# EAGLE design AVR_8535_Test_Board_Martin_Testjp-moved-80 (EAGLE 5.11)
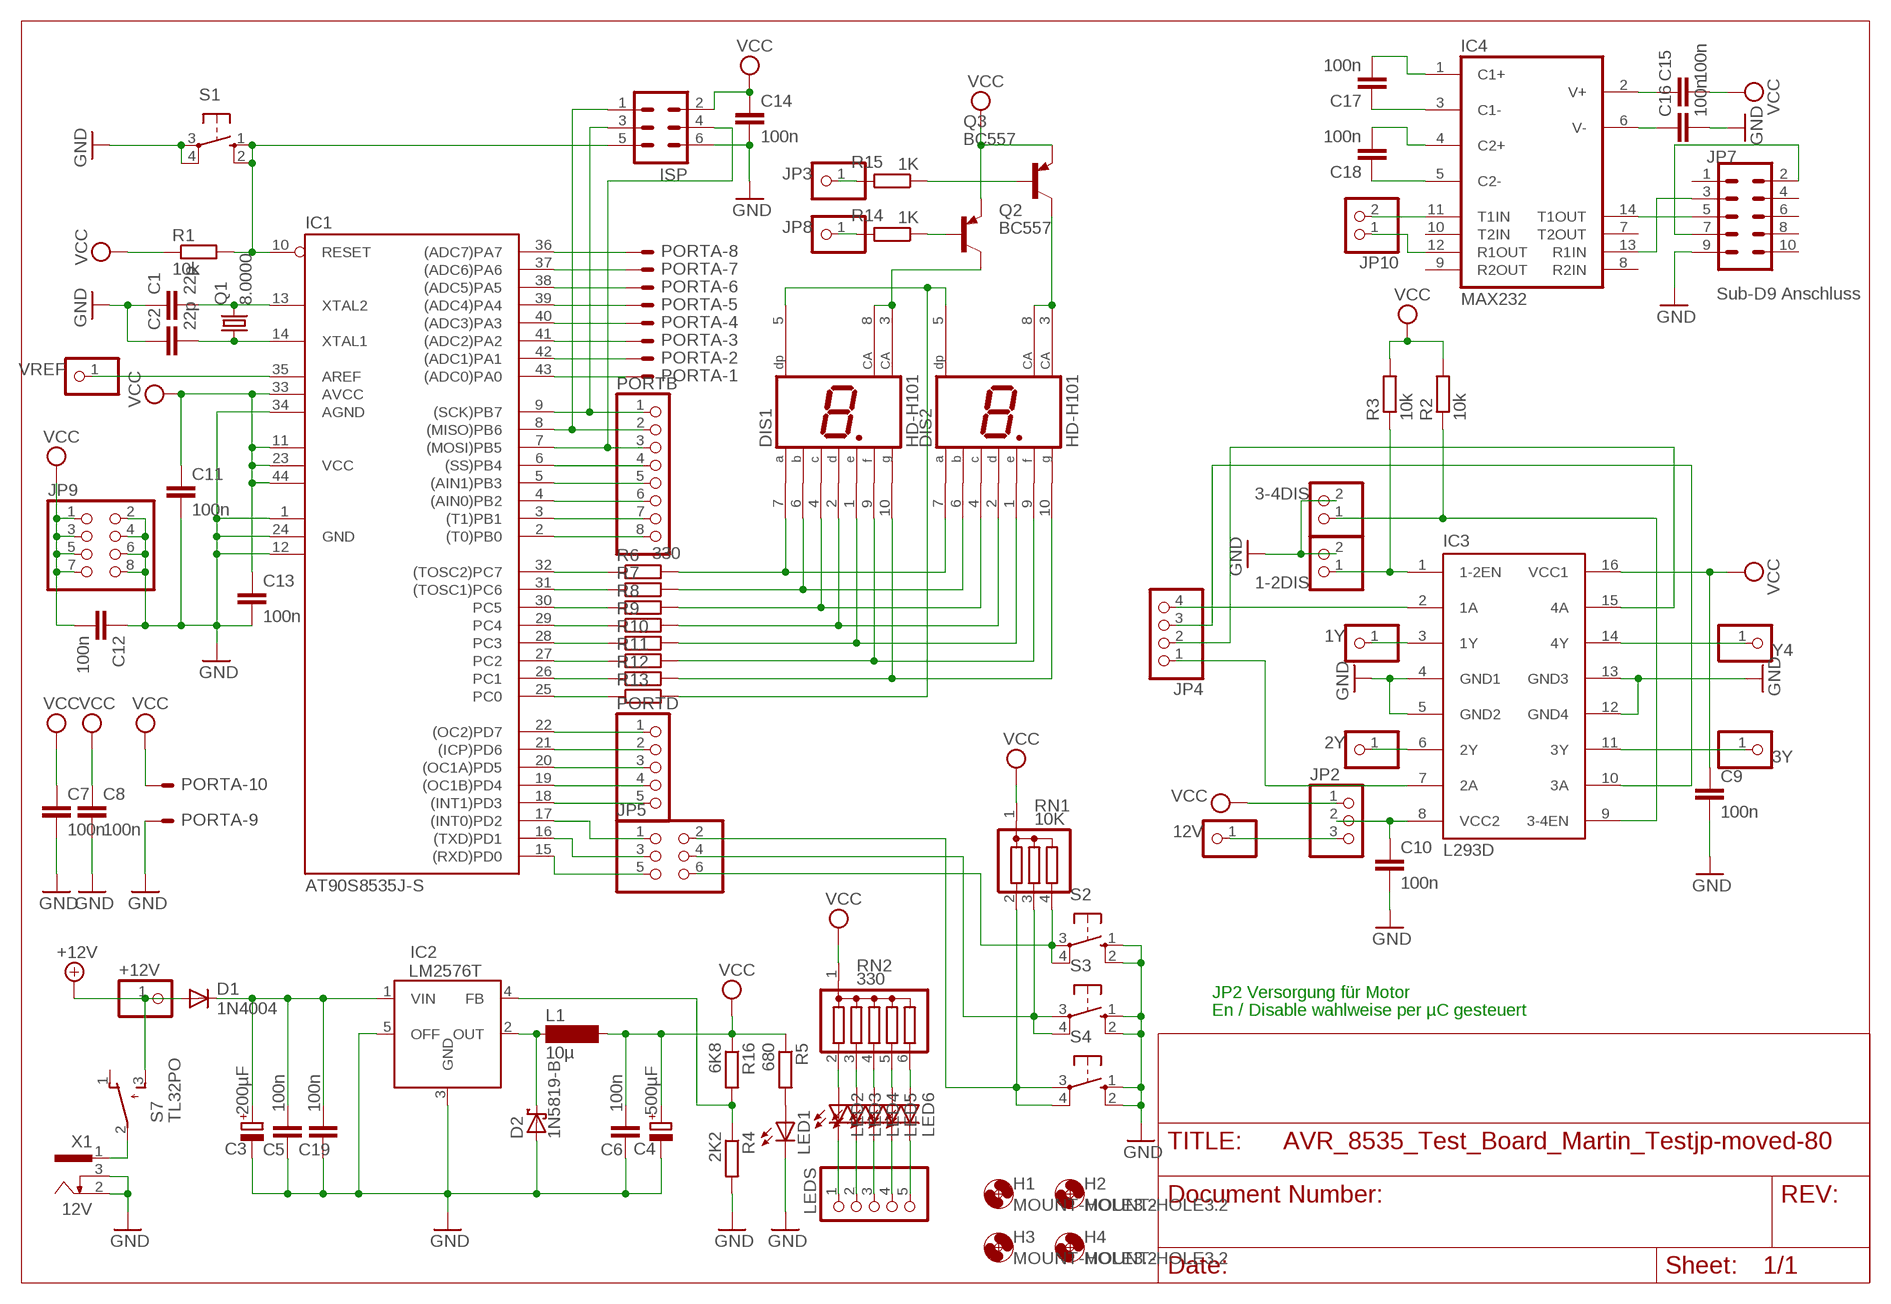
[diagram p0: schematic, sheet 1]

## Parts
1-2DIS  PINHD-1X2  [1X02]
1Y  PINHD-1X1  [1X01]
2Y  PINHD-1X1  [1X01]
3-4DIS  PINHD-1X2  [1X02]
3Y  PINHD-1X1  [1X01]
12V  PINHD-1X1  [1X01]
+12V  PINHD-1X1  [1X01]
C1  22p  C-EU025-024X044  [C025-024X044]
C2  22p  C-EU025-024X044  [C025-024X044]
C3  200µF  CPOL-EUE3.5-10  [E3,5-10]
C4  500µF  CPOL-EUE3.5-10  [E3,5-10]
C5  100n  C-EU050-024X044  [C050-024X044]
C6  100n  C-EU050-024X044  [C050-024X044]
C7  100n  C-EU025-024X044  [C025-024X044]
C8  100n  C-EU025-024X044  [C025-024X044]
C9  100n  C-EU050-024X044  [C050-024X044]
C10  100n  C-EU050-024X044  [C050-024X044]
C11  100n  C-EU050-024X044  [C050-024X044]
C12  100n  C-EU025-024X044  [C025-024X044]
C13  100n  C-EU025-024X044  [C025-024X044]
C14  100n  C-EU050-024X044  [C050-024X044]
C15  100n  C-EU025-024X044  [C025-024X044]
C16  100n  C-EU025-024X044  [C025-024X044]
C17  100n  C-EU050-024X044  [C050-024X044]
C18  100n  C-EU025-024X044  [C025-024X044]
C19  100n  C-EU050-024X044  [C050-024X044]
D1  1N4004  [DO41-10]
D2  1N5819-B  [DO41-7.6]
DIS1  HD-H101  [HDSP-M]
DIS2  HD-H101  [HDSP-M]
H1  MOUNT-HOLE3.2  [3,2]
H2  MOUNT-HOLE3.2  [3,2]
H3  MOUNT-HOLE3.2  [3,2]
H4  MOUNT-HOLE3.2  [3,2]
IC1  AT90S8535J-S  [S44]
IC2  LM2576T  [TO220-5]
IC3  L293D  [DIL16]
IC4  MAX232  [DIL16]
ISP  ML6  [ML6]
JP2  PINHD-1X3  [1X03]
JP3  PINHD-1X1  [1X01]
JP4  PINHD-1X4  [1X04]
JP5  PINHD-2X3  [2X03]
JP7  Sub-D9 Anschluss  ML10  [ML10]
JP8  PINHD-1X1  [1X01]
JP9  PINHD-2X4  [2X04]
JP10  PINHD-1X2  [1X02]
L1  10µ  SD75  [SD75]
LED1  LED3MM  [LED3MM]
LED2  LED3MM  [LED3MM]
LED3  LED3MM  [LED3MM]
LED4  LED3MM  [LED3MM]
LED5  LED3MM  [LED3MM]
LED6  LED3MM  [LED3MM]
LEDS  PINHD-1X5  [1X05]
PORTA  ML10E  [ML10]
PORTB  PINHD-1X8  [1X08]
PORTD  PINHD-1X5  [1X05]
Q1  8.0000  CRYSTALHC49U-V  [HC49U-V]
Q2  BC557  [TO92-EBC]
Q3  BC557  [TO92-EBC]
R1  10k  R-EU_0204/5  [0204/5]
R2  10k  R-EU_0204/5  [0204/5]
R3  10k  R-EU_0204/7  [0204/7]
R4  2K2  R-EU_0204/7  [0204/7]
R5  680  R-EU_0207/10  [0207/10]
R6  330  R-EU_0207/10  [0207/10]
R7  R-EU_0207/10  [0207/10]
R8  R-EU_0207/10  [0207/10]
R9  R-EU_0207/10  [0207/10]
R10  R-EU_0207/10  [0207/10]
R11  R-EU_0207/10  [0207/10]
R12  R-EU_0207/10  [0207/10]
R13  R-EU_0207/10  [0207/10]
R14  1K  R-EU_0204/2V  [0204V]
R15  1K  R-EU_0204/2V  [0204V]
R16  6K8  R-EU_0204/7  [0204/7]
RN1  10K  G03R  [SIL4]
RN2  330  G05R  [SIL6]
S1  10-XX  [B3F-10XX]
S2  10-XX  [B3F-10XX]
S3  10-XX  [B3F-10XX]
S4  10-XX  [B3F-10XX]
S7  TL32PO  [TL3XPO]
VREF  PINHD-1X1  [1X01]
X1  12V  SCD-014A  [SCD-014-A]
Y4  PINHD-1X1  [1X01]

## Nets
+12V: +12V.1 D1.A S7.3(S)
GND: 1-2DIS.2 3-4DIS.2 C1.1 C2.1 C3.- C4.- C5.2 C6.2 C7.2 C8.2 C9.2 C10.2 C11.2 C12.1 C13.2 C14.2 C16.2 C19.2 D2.A IC1.1(GND1) IC1.12(GND2) IC1.24(GND) IC1.34(AGND) IC2.3(GND) IC2.5(OFF) IC3.4(GND1) IC3.5(GND2) IC3.12(GND4) IC3.13(GND3) ISP.6 JP7.9 JP9.2 JP9.4 JP9.6 JP9.8 LED1.K(C) PORTA.9 R4.2 S1.3(P) S1.4(P1) S2.1(S) S2.2(S1) S3.1(S) S3.2(S1) S4.1(S) S4.2(S1) X1.2 X1.3
N$1: C10.1 IC3.8(VCC2) JP2.2
N$2: IC3.14(4Y) Y4.1
N$3: C3.+ C5.1 C19.1 D1.C IC2.1(VIN)
N$4: C1.2 IC1.13(XTAL2) Q1.2
N$5: C2.2 IC1.14(XTAL1) Q1.1
N$6: IC1.36((ADC7)PA7) PORTA.8
N$7: IC1.37((ADC6)PA6) PORTA.7
N$8: IC1.38((ADC5)PA5) PORTA.6
N$9: IC1.39((ADC4)PA4) PORTA.5
N$10: JP8.1 R14.2
N$11: IC1.2((T0)PB0) PORTB.8
N$12: IC3.2(1A) JP4.4
N$13: IC3.7(2A) JP4.1
N$14: IC3.10(3A) JP4.3
N$15: IC3.15(4A) JP4.2
N$16: IC1.8((MISO)PB6) ISP.1 PORTB.2
N$17: IC1.9((SCK)PB7) ISP.3 PORTB.1
N$18: IC1.40((ADC3)PA3) PORTA.4
N$19: IC1.41((ADC2)PA2) PORTA.3
N$20: IC1.42((ADC1)PA1) PORTA.2
N$21: IC1.43((ADC0)PA0) PORTA.1
N$22: LED1.A R5.2
N$23: IC1.32((TOSC2)PC7) R6.1
N$24: IC1.31((TOSC1)PC6) R7.1
N$25: IC1.30(PC5) R8.1
N$26: IC1.29(PC4) R9.1
N$27: IC1.28(PC3) R10.1
N$28: IC1.27(PC2) R11.1
N$29: IC1.26(PC1) R12.1
N$30: LED6.A RN2.6
N$31: JP5.6 RN1.4 S2.3(P) S2.4(P1)
N$32: C15.1 IC4.2(V+)
N$33: 3Y.1 IC3.11(3Y)
N$34: LED6.K(C) LEDS.5
N$35: 1Y.1 IC3.3(1Y)
N$36: 2Y.1 IC3.6(2Y)
N$37: JP5.4 RN1.3 S3.3(P) S3.4(P1)
N$38: JP5.2 RN1.2 S4.3(P) S4.4(P1)
N$39: IC1.25(PC0) R13.1
N$40: IC1.17((INT0)PD2) JP5.1
N$41: DIS1.7(A) DIS2.7(A) R6.2
N$42: DIS1.6(B) DIS2.6(B) R7.2
N$43: DIS1.4(C) DIS2.4(C) R8.2
N$44: DIS1.2(D) DIS2.2(D) R9.2
N$45: DIS1.1(E) DIS2.1(E) R10.2
N$46: DIS1.9(F) DIS2.9(F) R11.2
N$47: DIS1.10(G) DIS2.10(G) R12.2
N$48: DIS1.3(CA) DIS1.8(CA) Q2.C
N$49: DIS2.3(CA) DIS2.8(CA) Q3.C
N$50: DIS1.5(DP) DIS2.5(DP) R13.2
N$51: Q3.B R15.1
N$52: Q2.B R14.1
N$53: D2.C IC2.2(OUT) L1.1
N$54: 3-4DIS.1 IC3.9(3-4EN) R2.1
N$55: IC1.16((TXD)PD1) JP5.3
N$56: IC1.4((AIN0)PB2) PORTB.6
N$57: IC1.5((AIN1)PB3) PORTB.5
N$58: IC1.6((SS)PB4) PORTB.4
N$59: IC1.7((MOSI)PB5) ISP.4 PORTB.3
N$60: S7.2(P) X1.1
N$61: IC1.22((OC2)PD7) PORTD.1
N$62: IC1.21((ICP)PD6) PORTD.2
N$63: IC1.20((OC1A)PD5) PORTD.3
N$64: IC1.19((OC1B)PD4) PORTD.4
N$65: IC1.15((RXD)PD0) JP5.5
N$66: LED2.K(C) LEDS.1
N$67: LED3.K(C) LEDS.2
N$68: LED4.K(C) LEDS.3
N$69: 12V.1 JP2.3
N$70: JP3.1 R15.2
N$71: IC1.3((T1)PB1) PORTB.7
N$72: IC1.35(AREF) VREF.1
N$73: LED5.K(C) LEDS.4
N$74: IC1.18((INT1)PD3) PORTD.5
N$75: IC1.10(RESET) ISP.5 R1.2 S1.1(S) S1.2(S1)
N$76: C16.1 IC4.6(V-)
N$77: LED5.A RN2.5
N$78: LED4.A RN2.4
N$79: LED3.A RN2.3
N$80: LED2.A RN2.2
N$81: C17.1 IC4.3(C1-)
N$82: C17.2 IC4.1(C1+)
N$83: C18.1 IC4.5(C2-)
N$84: C18.2 IC4.4(C2+)
N$85: IC4.14(T1OUT) JP7.5
N$86: IC4.13(R1IN) JP7.3
N$87: JP7.2 JP7.7
N$88: IC4.11(T1IN) JP10.2
N$89: IC4.12(R1OUT) JP10.1
N$90: IC2.4(FB) R4.1 R16.2
N$92: 1-2DIS.1 IC3.1(1-2EN) R3.1
VCC: C4.+ C6.1 C7.1 C8.1 C9.1 C11.1 C12.2 C13.1 C14.1 C15.2 IC1.11(VCC1) IC1.23(VCC) IC1.33(AVCC) IC1.44(VCC2) IC3.16(VCC1) ISP.2 JP2.1 JP9.1 JP9.3 JP9.5 JP9.7 L1.2 PORTA.10 Q2.E Q3.E R1.1 R2.2 R3.2 R5.1 R16.1 RN1.1 RN2.1
Unconnected: IC4.7(T2OUT) IC4.8(R2IN) IC4.9(R2OUT) IC4.10(T2IN) JP7.1 JP7.4 JP7.6 JP7.8 JP7.10 S7.1(O)

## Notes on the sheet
- JP2 Versorgung für Motor
- En / Disable wahlweise per µC gesteuert

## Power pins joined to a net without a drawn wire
GND: IC4.15(GND)
VCC: IC4.16(VCC)

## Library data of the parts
1-2DIS 3-4DIS JP10 = pinhead:PINHD-1X2: PIN HEADER
1Y 2Y 3Y 12V +12V JP3 JP8 VREF Y4 = pinhead:PINHD-1X1: PIN HEADER
C1 C2 C7-C18 = rcl:C-EU: CAPACITOR, European symbol
C3 C4 = rcl:CPOL-EU: POLARIZED CAPACITOR, European symbol
C5 C6 C19 = resistor:C-EU: CAPACITOR, European symbol
D1 = diode:1N4004: DIODE
D2 = diode:1N581*: 1.0A SCHOTTKY BARRIER RECTIFIER
DIS1 DIS2 = display-hp:HD-H101: LED DISPLAY 1-character 7 segment, decimal point right; OC_FARNELL: unknown; OC_NEWARK: unknown
H1-H4 = holes:MOUNT-HOLE: MOUNTING HOLE with drill center marker
IC1 = atmel:AT90*8535: MICROCONTROLLER 8 Kbytes FLASH 512 bytes SRAM 512 bytes EEPROM UART 8-channel 10 bit ADC; OC_FARNELL: unknown; OC_NEWARK: unknown
IC2 = v-reg-JP:LM2576: National Semiconductor 3.0A "Simple Switcher"(c) 52kHz, Vout 1.23-37V (HV: 57V), Vin 40V (HV: 60V), 50µA standby current
IC3 = st-microelectronics:L293D: PUSH-PULL 4 CHANNEL DRIVER; MPN: L293D; OC_FARNELL: 9589619; OC_NEWARK: 56P8249
IC4 = maxim:MAX232: RS232 TRANSEIVER; MF: MAXIM; MPN: MAX232ACPE+; OC_FARNELL: 9723773; OC_NEWARK: 68K4544
ISP = con-harting-ml:ML6: HARTING; OC_FARNELL: unknown; OC_NEWARK: unknown
JP2 = pinhead:PINHD-1X3: PIN HEADER
JP4 = pinhead:PINHD-1X4: PIN HEADER
JP5 = pinhead:PINHD-2X3: PIN HEADER
JP7 = con-harting-ml:ML10: HARTING; OC_FARNELL: unknown; OC_NEWARK: unknown
JP9 = pinhead:PINHD-2X4: PIN HEADER
L1 = inductor-neosid:SD75: INDUCTOR; OC_FARNELL: unknown; OC_NEWARK: unknown
LED1-LED6 = led:LED: LED
LEDS PORTD = pinhead:PINHD-1X5: PIN HEADER
PORTA = con-harting-ml:ML10?E: HARTING; OC_FARNELL: unknown; OC_NEWARK: unknown
PORTB = pinhead:PINHD-1X8: PIN HEADER
Q1 = crystal:CRYSTAL: CRYSTAL; OC_FARNELL: 1666969; OC_NEWARK: unknown
Q2 Q3 = transistor-pnp:BC557*: PNP Transistror
R1-R16 = rcl:R-EU_: RESISTOR, European symbol
RN1 = resistor-sil:G03R: SIL RESISTOR; OC_FARNELL: unknown; OC_NEWARK: unknown
RN2 = resistor-sil:G05R: SIL RESISTOR; OC_FARNELL: unknown; OC_NEWARK: unknown
S1-S4 = switch-omron:10-XX: OMRON SWITCH; MPN: B3F-1000; OC_FARNELL: 176432; OC_NEWARK: 36M3542
S7 = switch:TL32PO: TINY SWITCH ON - MOM Source: http://www2.produktinfo.conrad.com/datenblaetter/700000-724999/705152-da-01-de-Subminiaturschalter_TL_36YO.pdf
X1 = con-shiua-chyuan:SCD-014A: Power Jack 2.5mm; OC_FARNELL: unknown; OC_NEWARK: unknown

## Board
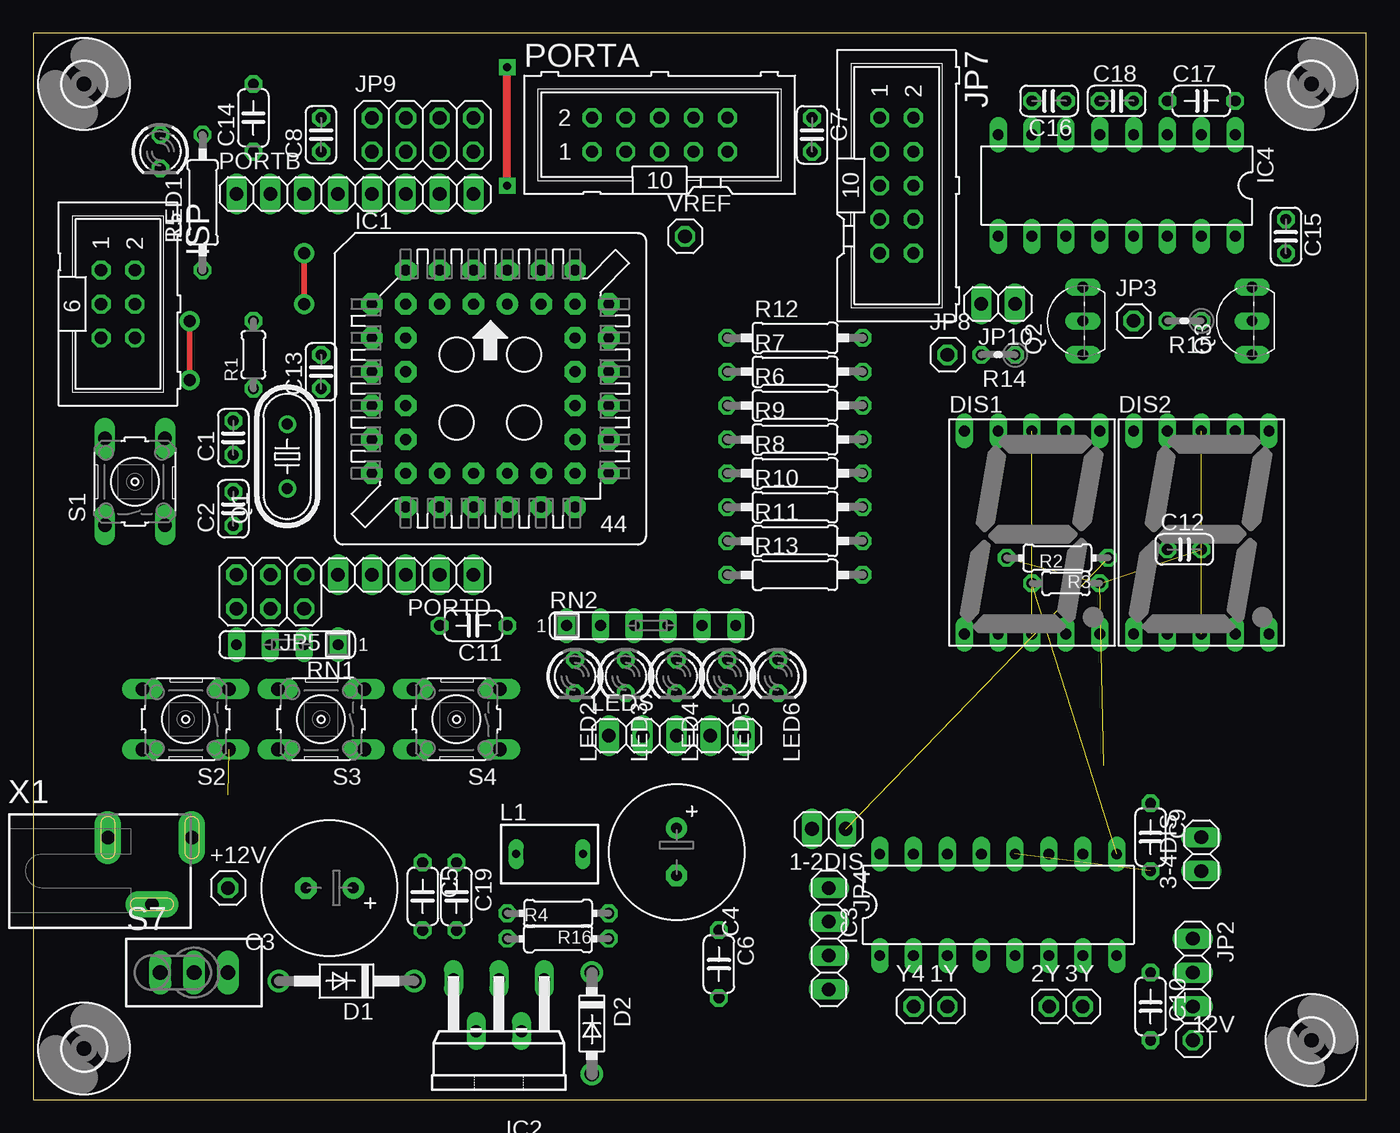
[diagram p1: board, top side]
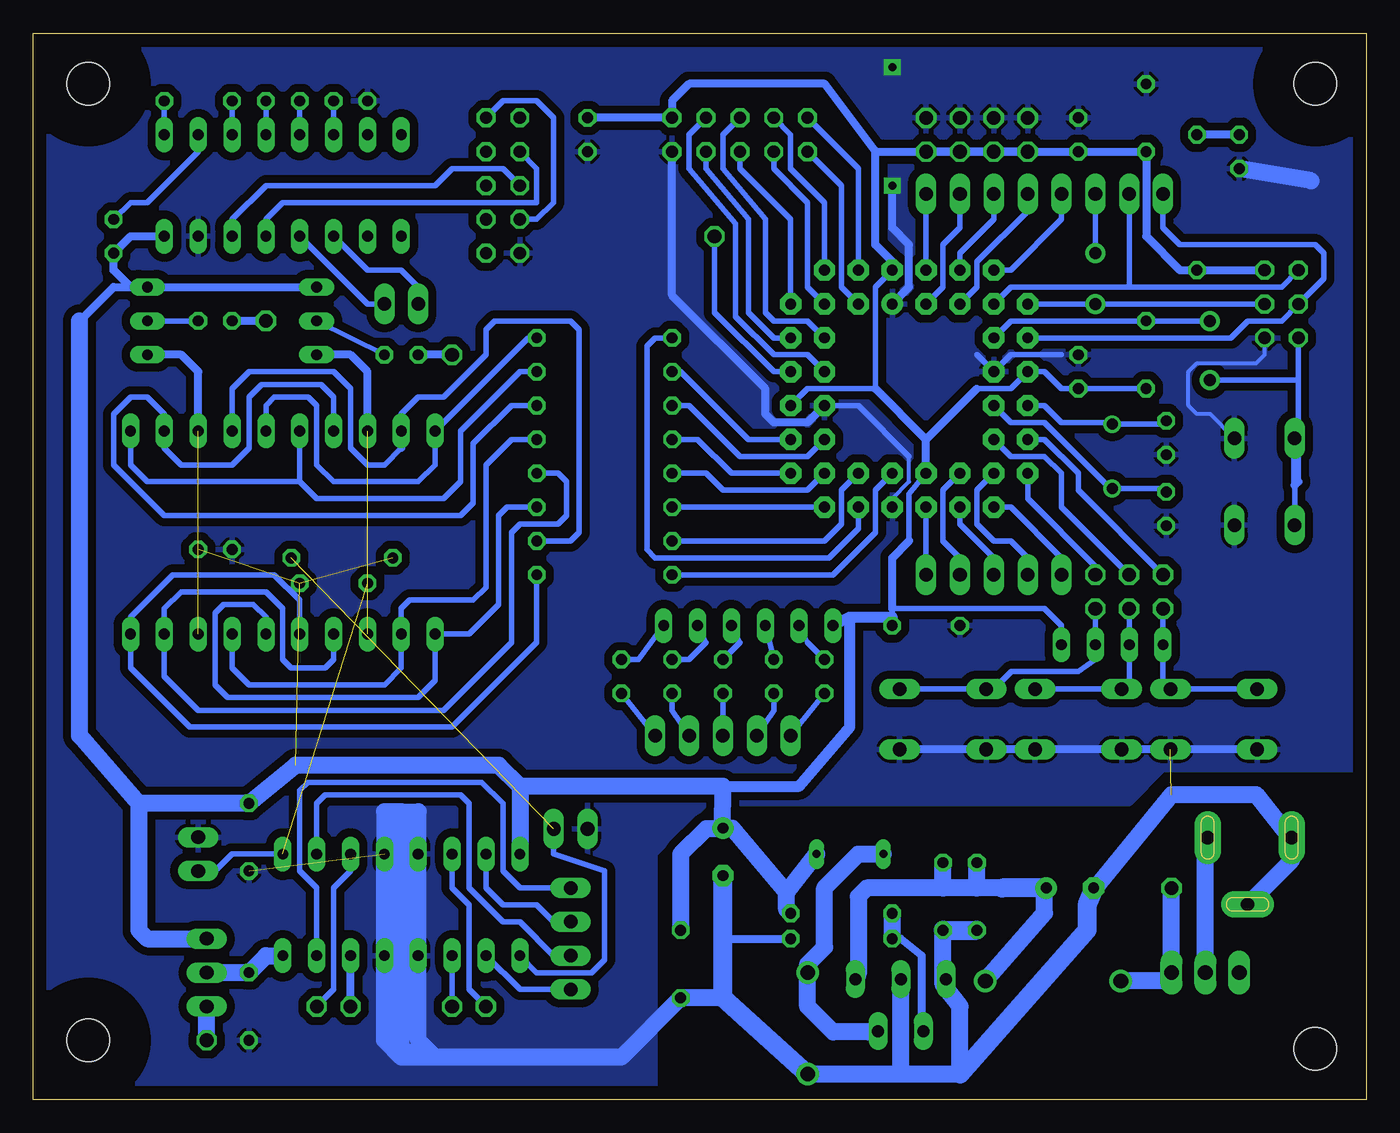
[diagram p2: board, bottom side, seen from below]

Size 100 x 80 mm. Coordinates in mm from the lower left corner, seen from the top.
Outline: 0,0 100,0 100,80 0,80 0,0
Copper layers (1*16): Top 0.035mm / dielectric 1.5mm / Bottom 0.035mm
Design rules "default *": minimum track width 10mil, minimum drill 24mil, track to track 8mil, track to pad 8mil, pad to pad 8mil, via to via 8mil, smd to smd 8mil, copper to edge 40mil, drill to drill 8mil, minimum pad ring 10mil, minimum via ring 12mil, stop-mask expansion 4mil, vias tented up to drill 0mil, thermal gap 10mil

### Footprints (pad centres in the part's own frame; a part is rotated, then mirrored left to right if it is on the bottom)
1X02 = drill 1.016 long: 1 -1.27,0; 2 1.27,0
1X01 = drill 1.016 octagon: 1 0,0
C025-024X044 = drill 0.813 octagon: 1 -1.27,0; 2 1.27,0
E3,5-10 = drill 0.813 pad 1.6 round: + -1.778,0 | drill 0.813 pad 1.6 octagon: - 1.778,0
C050-024X044 = drill 0.813 octagon: 1 -2.54,0; 2 2.54,0
DO41-10 = drill 1.118 round: A 5.08,0; C -5.08,0
DO41-7.6 = drill 1.1 pad 1.7 round: A 3.81,0; C -3.81,0
HDSP-M = drill 0.813 long: 1 -5.08,-7.62; 2 -2.54,-7.62; 3 0,-7.62; 4 2.54,-7.62; 5 5.08,-7.62; 6 5.08,7.62; 7 2.54,7.62; 8 0,7.62; 9 -2.54,7.62; 10 -5.08,7.62
3,2 = hole 3.2: 0,0
S44 = drill 0.813 pad 1.6 round: 1 1.27,6.35 | drill 0.813 pad 1.6 octagon: 2 -1.27,8.89; 3 -1.27,6.35; 4 -3.81,8.89; 5 -3.81,6.35; 6 -6.35,8.89; 7 -8.89,6.35; 8 -6.35,6.35; 9 -8.89,3.81; 10 -6.35,3.81; 11 -8.89,1.27; 12 -6.35,1.27; 13 -8.89,-1.27; 14 -6.35,-1.27; 15 -8.89,-3.81; 16 -6.35,-3.81; 17 -8.89,-6.35; 18 -6.35,-8.89; 19 -6.35,-6.35; 20 -3.81,-8.89; 21 -3.81,-6.35; 22 -1.27,-8.89; 23 -1.27,-6.35; 24 1.27,-8.89; 25 1.27,-6.35; 26 3.81,-8.89; 27 3.81,-6.35; 28 6.35,-8.89; 29 8.89,-6.35; 30 6.35,-6.35; 31 8.89,-3.81; 32 6.35,-3.81; 33 8.89,-1.27; 34 6.35,-1.27; 35 8.89,1.27; 36 6.35,1.27; 37 8.89,3.81; 38 6.35,3.81; 39 8.89,6.35; 40 6.35,8.89; 41 6.35,6.35; 42 3.81,8.89; 43 3.81,6.35; 44 1.27,8.89
TO220-5 = drill 0.9 long: 1 -3.4,-5.86; 2 -1.7,-1.96; 3 0,-5.86; 4 1.7,-1.96; 5 3.4,-5.86
DIL16 = drill 0.813 long: 1 -8.89,-3.81; 2 -6.35,-3.81; 3 -3.81,-3.81; 4 -1.27,-3.81; 5 1.27,-3.81; 6 3.81,-3.81; 7 6.35,-3.81; 8 8.89,-3.81; 9 8.89,3.81; 10 6.35,3.81; 11 3.81,3.81; 12 1.27,3.81; 13 -1.27,3.81; 14 -3.81,3.81; 15 -6.35,3.81; 16 -8.89,3.81
ML6 = drill 0.914 octagon: 1 -2.54,-1.27; 2 -2.54,1.27; 3 0,-1.27; 4 0,1.27; 5 2.54,-1.27; 6 2.54,1.27
1X03 = drill 1.016 long: 1 -2.54,0; 2 0,0; 3 2.54,0
1X04 = drill 1.016 long: 1 -3.81,0; 2 -1.27,0; 3 1.27,0; 4 3.81,0
2X03 = drill 1.016 octagon: 1 -2.54,-1.27; 2 -2.54,1.27; 3 0,-1.27; 4 0,1.27; 5 2.54,-1.27; 6 2.54,1.27
ML10 = drill 0.914 octagon: 1 -5.08,-1.27; 2 -5.08,1.27; 3 -2.54,-1.27; 4 -2.54,1.27; 5 0,-1.27; 6 0,1.27; 7 2.54,-1.27; 8 2.54,1.27; 9 5.08,-1.27; 10 5.08,1.27
2X04 = drill 1.016 octagon: 1 -3.81,-1.27; 2 -3.81,1.27; 3 -1.27,-1.27; 4 -1.27,1.27; 5 1.27,-1.27; 6 1.27,1.27; 7 3.81,-1.27; 8 3.81,1.27
SD75 = drill 0.6 long: 1 -2.5,0; 2 2.5,0
LED3MM = drill 0.813 octagon: A -1.27,0; K 1.27,0
1X05 = drill 1.016 long: 1 -5.08,0; 2 -2.54,0; 3 0,0; 4 2.54,0; 5 5.08,0
1X08 = drill 1.016 long: 1 -8.89,0; 2 -6.35,0; 3 -3.81,0; 4 -1.27,0; 5 1.27,0; 6 3.81,0; 7 6.35,0; 8 8.89,0
HC49U-V = drill 0.813 round: 1 -2.413,0; 2 2.413,0
TO92-EBC = drill 0.813 long: B 0,-1.27; C -2.54,-1.27; E 2.54,-1.27
0204/5 = drill 0.813 octagon: 1 -2.54,0; 2 2.54,0
0204/7 = drill 0.813 octagon: 1 -3.81,0; 2 3.81,0
0207/10 = drill 0.813 octagon: 1 -5.08,0; 2 5.08,0
0204V = drill 0.813 octagon: 1 -1.27,0; 2 1.27,0
SIL4 = drill 0.813 long: 1 -3.81,0; 2 -1.27,0; 3 1.27,0; 4 3.81,0
SIL6 = drill 0.813 long: 1 -6.35,0; 2 -3.81,0; 3 -1.27,0; 4 1.27,0; 5 3.81,0; 6 6.35,0
B3F-10XX = drill 1.016 long: 1 -3.251,2.261; 2 3.251,2.261; 3 -3.251,-2.261; 4 3.251,-2.261
TL3XPO = drill 1.1 pad 1.422 long: 1 -2.54,0; 2 0,0; 3 2.54,0
SCD-014-A = drill 1 pad 2 long: 1 -2.5,13.8; 2 -2.5,7.5; 3 2.5,10.8

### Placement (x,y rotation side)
1-2DIS  59.69,20.3 180 top
1Y  68.58,6.99 0 top
2Y  76.2,6.99 0 top
3-4DIS  87.63,18.41 90 top
3Y  78.74,6.99 0 top
12V  87,4.45 0 top
+12V  14.61,15.88 0 top
C1  15,49.65 90 top
C2  15,44.32 90 top
C3  22.23,15.88 180 top
C4  48.26,18.58 270 top
C5  29.21,15.24 270 top
C6  51.44,10.16 270 top
C7  58.42,72.39 270 top
C8  21.59,72.39 90 top
C9  83.82,19.68 270 top
C10  83.82,6.99 270 top
C11  33.02,35.56 180 top
C12  86.36,41.27 0 top
C13  21.59,54.61 90 top
C14  16.51,73.66 90 top
C15  93.98,64.77 270 top
C16  76.2,74.93 180 top
C17  87.63,74.93 0 top
C18  81.28,74.93 0 top
C19  31.75,15.24 270 top
D1  23.5,8.89 180 top
D2  41.91,5.71 270 top
DIS1  74.93,42.55 0 top
DIS2  87.63,42.55 0 top
H1  3.81,3.81 0 top
H2  95.89,4.45 0 top
H3  3.81,76.2 0 top
H4  95.89,76.2 0 top
IC1  34.29,53.34 0 top
IC2  34.92,3.17 180 top
IC3  72.39,14.61 0 top
IC4  81.28,68.58 180 top
ISP  6.35,59.69 270 top
JP2  87,9.53 270 top
JP3  82.55,58.42 0 top
JP4  59.69,12.06 270 top
JP5  17.78,38.1 180 top
JP7  64.77,68.58 270 top
JP8  68.58,55.88 0 top
JP9  29.21,72.39 0 top
JP10  72.39,59.69 180 top
L1  38.73,18.41 0 top
LED1  9.53,71.12 270 top
LED2  40.64,31.75 270 top
LED3  44.45,31.75 270 top
LED4  48.26,31.75 270 top
LED5  52.07,31.75 270 top
LED6  55.88,31.75 270 top
LEDS  48.26,27.3 0 top
PORTA  46.99,72.39 0 top
PORTB  24.13,67.94 0 top
PORTD  27.94,39.37 180 top
Q1  19.05,48.26 90 top
Q2  77.47,58.42 90 top
Q3  90.17,58.42 90 top
R1  16.51,55.88 90 top
R2  77.47,38.73 0 top
R3  76.83,40.64 180 top
R4  39.37,12.06 0 top
R5  12.7,67.31 90 top
R6  57.15,52.07 0 top
R7  57.15,54.61 0 top
R8  57.15,46.99 0 top
R9  57.15,49.53 0 top
R10  57.15,44.45 0 top
R11  57.15,41.91 0 top
R12  57.15,57.15 0 top
R13  57.15,39.37 0 top
R14  72.39,55.88 180 top
R15  86.36,58.42 180 top
R16  39.37,13.97 180 top
RN1  19.05,34.13 180 top
RN2  46.35,35.56 0 top
S1  7.62,46.35 90 top
S2  11.43,28.53 180 top
S3  21.59,28.53 180 top
S4  31.75,28.53 180 top
S7  12.06,9.53 0 top
VREF  48.9,64.77 0 top
X1  -1.91,17.14 270 top
Y4  66.04,6.99 0 top

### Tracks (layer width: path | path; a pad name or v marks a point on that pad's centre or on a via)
+12V
  Bottom 1.27: +12V.1 S7.3 14.61,8.89 D1.A
GND  (via drill 0.6)  (2 unrouted)
  Top 0.61: v35.56,68.58 v35.56,77.47
  Bottom 0.305: 35.56,44.98 IC1.24 35.56,45.09 34.29,46.35 34.29,48.26 | ISP.6 7.62,55.88 8.26,55.24 12.7,55.24 13.34,54.61 13.34,52.07 12.7,51.44 11.71,51.44 S1.4
  Bottom 0.406: 22.86,55.88 26.67,55.88 IC1.12 29.21,55.88 | 34.29,48.26 38.1,52.07 IC1.34
  Bottom 0.61: C4.- 48.26,12.06 R4.2 | S4.1 S4.2 S3.1 S3.2 S2.1 S2.2 | IC1.1 34.29,60.96 34.29,64.14 35.56,65.41 v35.56,68.58 | IC1.34 41.91,50.8 44.45,50.8 45.09,51.44 45.09,53.34 52.07,60.33 PORTA.9 | X1.2 5.67,19.64 5.71,19.68 | 34.92,8.89 IC2.3 | 20.32,15.88 C3.-
  Bottom 1.27: 4.13,68.94 LED1.K | 34.92,1.91 34.92,8.89 | 31.75,8.62 C19.2 | 34.92,1.91 30.48,1.91 30.48,6.99 31.75,8.62 | 34.92,1.91 D2.A | X1.2 5.59,17.95 X1.3 | 31.75,8.62 IC2.5 | 20.32,15.88 14.61,22.86 8.26,22.86 5.71,19.68 | 48.26,7.62 C6.2 55.88,3.17 69.85,3.17 | 69.85,3.17 71.12,4.45 IC3.4 IC3.13 71.12,21.59 72.39,21.59 | 72.39,21.59 73.66,21.59 IC3.12 IC3.5 73.66,4.45 72.39,3.17 71.12,3.17 | 69.85,3.17 71.12,3.17 | 71.12,3.17 72.39,3.81 72.39,21.59
  Bottom 1.422: D2.A 48.26,7.62 C4.- | C3.- 20.95,14.61 20.95,12.7 30.48,1.91 | C19.2 C5.2
  pour Bottom (isolate 0.61): 0,24.77 0,80.64 100.33,80.64 100.33,0 53.34,0 53.34,18.41 49.53,22.23 17.78,22.23 15.24,24.77
N$1
  Bottom 1.27: IC3.8 82.55,10.79 C10.1 JP2.2
N$2
  Bottom 0.406: IC3.14 68.58,15.88 67.31,14.61 67.31,8.26 Y4.1
N$3
  Bottom 1.27: 27.3,15.88 29.21,15.88 | 29.21,15.88 31.75,15.88 | 31.75,15.88 37.47,15.88 38.1,15.24 38.1,9.45 IC2.1 | 31.75,15.88 C19.1 | 29.21,15.88 C5.1 | D1.C 24.13,13.97 24.13,15.88
  Bottom 1.422: 27.3,15.88 24.13,15.88 C3.+
N$4
  Bottom 0.406: C1.2 15,50.67 Q1.2 19.18,50.8 22.86,50.8 24.13,52.07 IC1.13
N$5
  Bottom 0.305: Q1.1 19.18,45.85
  Bottom 0.406: 19.18,45.85 24.13,50.8 26.67,50.8 IC1.14 | Q1.1 15,45.85 C2.2
N$6
  Bottom 0.406: IC1.36 41.91,55.88 44.45,55.88 47.31,58.74 47.31,65.72 50.8,69.85 50.8,72.39 PORTA.8
N$7
  Bottom 0.406: PORTA.7 49.53,69.85 46.35,66.04 46.35,59.05 44.45,57.15 IC1.37
N$8
  Bottom 0.406: IC1.38 41.91,58.42 44.45,58.42 45.09,59.05 45.09,66.04 48.26,69.85 48.26,72.39 PORTA.6
N$9
  Bottom 0.406: PORTA.5 46.99,69.85 43.18,66.04 IC1.39
N$10
  Bottom 0.61: JP8.1 R14.2
N$11
  Bottom 0.406: IC1.2 PORTB.8
N$12
  Bottom 0.406: IC3.2 63.5,8.26 JP4.4
N$13
  Bottom 0.406: IC3.7 78.74,15.88 80.01,17.14 80.01,23.18 79.38,23.81 66.36,23.81 64.77,22.23 64.77,17.14 63.5,15.88 JP4.1
N$14
  Bottom 0.406: IC3.10 78.74,22.23 78.11,22.86 67.94,22.86 67.31,22.23 67.31,15.88 64.77,13.34 63.5,13.34 60.96,10.79 JP4.3
N$15
  Bottom 0.406: IC3.15 66.04,15.88 64.77,14.61 62.23,14.61 60.96,13.34 JP4.2
N$16
  Bottom 0.406: ISP.1 6.35,60.96 17.78,60.96 | 17.78,60.96 26.67,60.96 IC1.8 | 17.78,60.96 PORTB.2
N$17
  Bottom 0.406: PORTB.1 15.24,65.41 13.97,64.14 3.81,64.14 3.17,63.5 3.17,61.59 ISP.3 6.35,58.42 8.89,58.42 10.16,57.15 IC1.9
N$18
  Bottom 0.406: PORTA.4 43.18,72.39 43.18,69.85 40.64,67.31 IC1.40
N$19
  Bottom 0.406: PORTA.3 44.45,69.85 41.91,67.31 41.91,60.96 IC1.41
N$20
  Bottom 0.406: PORTA.2 38.1,69.85 IC1.42
N$21
  Bottom 0.406: IC1.43 39.37,60.96 39.37,68.58 PORTA.1
N$22
  Bottom 0.61: LED1.A R5.2
N$23
  Bottom 0.406: R6.1 50.8,52.07 46.99,48.26 41.91,48.26 IC1.32
N$24
  Bottom 0.406: IC1.31 46.35,49.53 51.44,54.61 R7.1
N$25
  Bottom 0.406: IC1.30 41.91,45.72 48.26,45.72 49.53,46.99 R8.1
N$26
  Bottom 0.406: IC1.29 47.62,46.99 50.16,49.53 R9.1
N$27
  Bottom 0.406: IC1.28 R10.1
N$28
  Bottom 0.406: IC1.27 39.37,45.72 39.37,43.18 40.64,41.91 R11.1
N$29
  Bottom 0.406: IC1.26 38.1,42.86 40.32,40.64 53.34,40.64 53.98,41.27 53.98,56.52 53.34,57.15 R12.1
N$30
  Bottom 0.406: RN2.6 54.61,33.02 LED6.A
N$31
  Bottom 0.406: S2.4 S2.3 15.24,31.35 RN1.4 JP5.6
N$32
  Bottom 0.406: IC4.2 87.63,71.12 91.44,67.31 92.71,67.31 C15.1
N$33
  Bottom 0.406: IC3.11 76.2,17.14 77.47,15.88 77.47,8.26 3Y.1
N$34
  Bottom 0.406: LEDS.5 LED6.K
N$35
  Bottom 0.406: 1Y.1 IC3.3
N$36
  Bottom 0.61: 2Y.1 IC3.6
N$37
  Bottom 0.406: S3.3 S3.4 17.78,31.35 RN1.3 JP5.4
N$38
  Bottom 0.406: S4.3 S4.4 27.94,30.79 | 27.94,30.79 27.47,30.79 | JP5.2 RN1.2 20.32,33.02 21.59,32.13 26.6,32.13 27.94,30.79
N$39
  Bottom 0.406: IC1.25 36.83,45.72 36.83,42.55 40.01,39.37 R13.1
N$40
  Bottom 0.406: IC1.17 25.4,45.09 20.32,40.01 JP5.1
N$41
  Bottom 0.406: DIS1.7 77.47,52.7 78.42,53.66 82.87,53.66 83.82,52.7 83.82,48.9 85.09,47.62 88.9,47.62 90.17,48.9 DIS2.7 90.17,51.44 91.44,52.7 92.71,52.7 93.98,51.44 93.98,47.62 90.17,43.81 67.94,43.81 66.99,44.77 66.99,49.21 64.14,52.07 R6.2
N$42
  Bottom 0.406: 80.01,46.35 DIS1.6 | 80.01,46.35 91.44,46.35 92.71,47.62 DIS2.6 | R7.2 63.5,54.61 67.94,50.16 67.94,46.35 69.22,45.09 78.74,45.09 80.01,46.35
N$43
  Bottom 0.406: R8.2 60.64,46.99 60.01,46.35 60.01,43.81 60.64,43.18 63.5,43.18 64.14,42.55 64.14,34.29 69.22,29.21 87.63,29.21 90.17,31.75 DIS2.4 90.17,36.83 88.9,38.1 82.55,38.1 81.28,36.83 81.28,33.02 80.64,32.38 78.11,32.38 77.47,33.02 DIS1.4
N$44
  Bottom 0.406: DIS2.2 85.09,32.38 83.82,31.11 73.66,31.11 72.39,32.38 DIS1.2 | DIS1.2 72.39,36.83 71.75,37.47 66.99,37.47 66.04,38.42 66.04,47.62 64.14,49.53 R9.2 | DIS1.2 72.39,34.29
N$45
  Bottom 0.406: DIS2.1 82.55,36.2 83.5,37.15 85.72,37.15 86.36,36.51 86.36,31.11 85.41,30.16 71.12,30.16 69.85,31.43 DIS1.1 67.31,34.92 65.09,37.15 65.09,43.81 64.45,44.45 R10.2
N$46
  Bottom 0.406: 72.39,48.9 73.66,47.62 74.93,47.62 76.2,48.9 76.2,53.34 77.47,54.61 83.82,54.61 85.09,53.34 DIS2.9 | R11.2 59.69,41.91 59.05,42.55 59.05,57.78 59.69,58.42 65.41,58.42 66.04,57.78 66.04,55.88 69.22,52.7 71.12,52.7 72.39,51.44 DIS1.9
  Bottom 0.61: DIS1.9 72.39,48.9
N$47
  Bottom 0.406: DIS2.10 82.55,52.07 81.92,52.7 79.38,52.7 78.74,52.07 78.74,47.62 77.47,46.35 71.12,46.35 69.85,47.62 DIS1.10 62.87,57.15 R12.2
N$48  (1 unrouted)
  Bottom 0.61: DIS1.8 74.93,54.61 76.2,55.88 Q2.C
N$49  (1 unrouted)
  Bottom 0.61: Q3.C 88.9,55.88 87.63,54.61 DIS2.8
N$50
  Bottom 0.406: DIS1.5 80.01,37.47 81.92,39.37 89.53,39.37 92.71,36.2 DIS2.5 92.71,32.38 88.27,27.94 68.58,27.94 62.23,34.29 R13.2
N$51
  Bottom 0.406: R15.1 Q3.B
N$52
  Bottom 0.406: R14.1 Q2.B
N$53
  Bottom 1.27: IC2.2 37.31,5.08 40.01,5.08 41.91,6.99 D2.C 41.91,10.16 40.64,11.43 40.64,15.88 38.1,18.41 L1.1
N$54  (1 unrouted)
  Bottom 0.406: IC3.9 85.09,18.41 86.36,17.14 3-4DIS.1
N$55
  Bottom 0.406: IC1.16 26.67,48.26 24.13,48.26 22.86,46.99 22.86,44.45 JP5.3
N$56
  Bottom 0.406: PORTB.6 27.94,66.04 30.48,63.5 IC1.4
N$57
  Bottom 0.406: IC1.5 29.21,60.96 29.21,62.87 25.4,66.67 PORTB.5
N$58
  Bottom 0.406: IC1.6 26.67,62.23 22.86,66.04 PORTB.4
N$59  (via drill 0.9)
  Top 0.406: v20.32,59.69 v20.32,63.5
  Bottom 0.406: ISP.4 v20.32,59.69 IC1.7 | v20.32,63.5 PORTB.3
N$60
  Bottom 1.016: 12.06,19.48 X1.1
  Bottom 1.27: S7.2 12.06,19.48
N$61
  Bottom 0.406: PORTD.1 IC1.22
N$62
  Bottom 0.406: IC1.21 31.75,45.72 31.75,41.91 30.48,40.64 PORTD.2
N$63
  Bottom 0.406: IC1.20 30.48,43.18 27.94,40.64 PORTD.3
N$64
  Bottom 0.406: IC1.19 29.21,45.72 29.21,43.18 27.94,41.91 26.67,41.91 25.4,40.64 PORTD.4
N$65
  Bottom 0.406: IC1.15 24.13,49.53 21.59,46.99 21.59,45.72 JP5.5
N$66
  Bottom 0.406: LEDS.1 LED2.K
N$67
  Bottom 0.406: LED3.K 44.45,29.21 LEDS.2
N$68
  Bottom 0.406: LEDS.3 LED4.K
N$69
  Bottom 1.27: 87.63,6.99 JP2.3 12V.1
N$70
  Bottom 0.61: JP3.1 R15.2
N$71
  Bottom 0.406: IC1.3 31.75,60.96 31.75,64.14 30.48,65.41 PORTB.7
N$72
  Bottom 0.406: IC1.35 44.45,54.61 48.9,59.05 VREF.1
N$73
  Bottom 0.406: LED5.K 52.07,29.21 LEDS.4
N$74
  Bottom 0.406: PORTD.5 22.86,40.64 26.67,44.45 IC1.18
N$75  (via drill 0.9)
  Top 0.406: v11.73,53.98 v11.73,58.42
  Bottom 0.406: S1.1 S1.2 | IC1.10 26.67,58.42 R1.2 v11.73,58.42 | 5.08,53.98 ISP.5 | 5.08,53.98 v11.73,53.98 | 5.08,46.35 5.08,53.98
  Bottom 0.61: S1.2 5.36,46.08 5.08,46.35
N$76
  Bottom 0.406: IC4.6 C16.1
N$77
  Bottom 0.406: RN2.5 49.53,34.29 50.8,33.02 LED5.A
N$78
  Bottom 0.406: RN2.4 46.99,34.29 LED4.A
N$79
  Bottom 0.406: LED3.A RN2.3
N$80
  Bottom 0.406: RN2.2 41.91,34.29 LED2.A
N$81
  Bottom 0.406: IC4.3 C17.1
N$82
  Bottom 0.406: IC4.1 C17.2
N$83
  Bottom 0.406: IC4.5 C18.1
N$84
  Bottom 0.406: IC4.4 C18.2
N$85
  Bottom 0.406: JP7.5 64.77,69.85 68.58,69.85 69.85,68.58 82.55,68.58 85.09,66.04 IC4.14
N$86
  Bottom 0.406: JP7.3 62.23,69.85 62.23,67.31 81.28,67.31 82.55,66.04 IC4.13
N$87
  Bottom 0.406: JP7.2 64.77,74.93 62.23,74.93 60.96,73.66 60.96,67.31 62.23,66.04 JP7.7
N$88
  Bottom 0.406: IC4.11 74.93,62.23 72.39,62.23 71.12,60.96 JP10.2
N$89
  Bottom 0.406: IC4.12 74.93,59.69 JP10.1
N$90
  Bottom 0.61: R4.1 34.92,12.06 33.34,10.79 33.34,5.08 33.17,5.08 IC2.4
  Bottom 1.27: R4.1 R16.2
N$92  (1 unrouted)
  Bottom 0.406: IC3.1 62.23,9.53 58.1,9.53 57.15,10.48 57.15,17.14 60.96,18.41 1-2DIS.1
VCC  (3 unrouted)
  Bottom 0.406: IC1.23 34.29,45.42 34.29,41.91 | 29.21,53.34 26.67,53.34 IC1.11 24.13,54.61 22.86,53.34 C13.1 R1.1 | IC1.33 41.91,53.34 36.83,53.34 36.83,60.96 IC1.44 | 35.56,36.2 C11.1 35.56,36.83 24.13,36.83 22.86,35.56 RN1.1
  Bottom 0.61: 33.02,49.53 29.21,53.34 | IC1.23 33.02,49.53 | 33.02,49.53 36.83,53.34 | Q2.E Q3.E 92.71,60.96 | JP9.1 JP9.3 JP9.5 JP9.7 JP9.1 | C7.1 PORTA.10 52.07,74.93 50.8,76.2 40.64,76.2 36.83,71.12 | 96.52,58.42 93.98,60.96 92.71,60.96 | ISP.2 R5.1 13.97,62.23 16.51,64.77 C14.1 C8.1 JP9.1 | IC1.44 35.56,62.87 36.83,64.14 36.83,71.12 | 36.83,71.12 JP9.1 | IC4.16 92.71,64.77 C15.2 93.98,62.23 92.71,60.96 | 35.56,36.83 35.56,40.64 34.29,41.91
  Bottom 0.813: 38.73,36.2 RN2.1 | 48.26,23.5 42.55,23.5 38.73,27.94 38.73,36.2 | 38.73,36.2 35.56,36.2
  Bottom 1.016: C4.+ 48.3,20.36
  Bottom 1.27: 96.52,58.42 96.52,27.3 92.08,22.23 | 43.48,15.54 L1.2 | 43.48,15.54 47.55,20.36 C4.+ 48.3,20.32 49.53,20.32 51.44,18.41 C6.1 | R16.1 43.48,14.27 43.48,15.54 | 63.5,23.5 IC3.16 | 63.5,23.5 48.26,23.5 48.3,20.36 | 63.5,23.5 65.09,25.08 80.33,25.08 C9.1 92.08,22.23 | 92.08,22.23 92.08,12.7 91.44,12.06 JP2.1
